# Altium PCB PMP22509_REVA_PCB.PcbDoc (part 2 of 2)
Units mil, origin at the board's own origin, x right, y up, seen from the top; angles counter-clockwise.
Board outline 3681.1 x 1505.91 mil, 2 copper layers (Top Layer, Bottom Layer), stack 62 mil thick; 70 components, 35 nets, 219 pads, 81 vias.
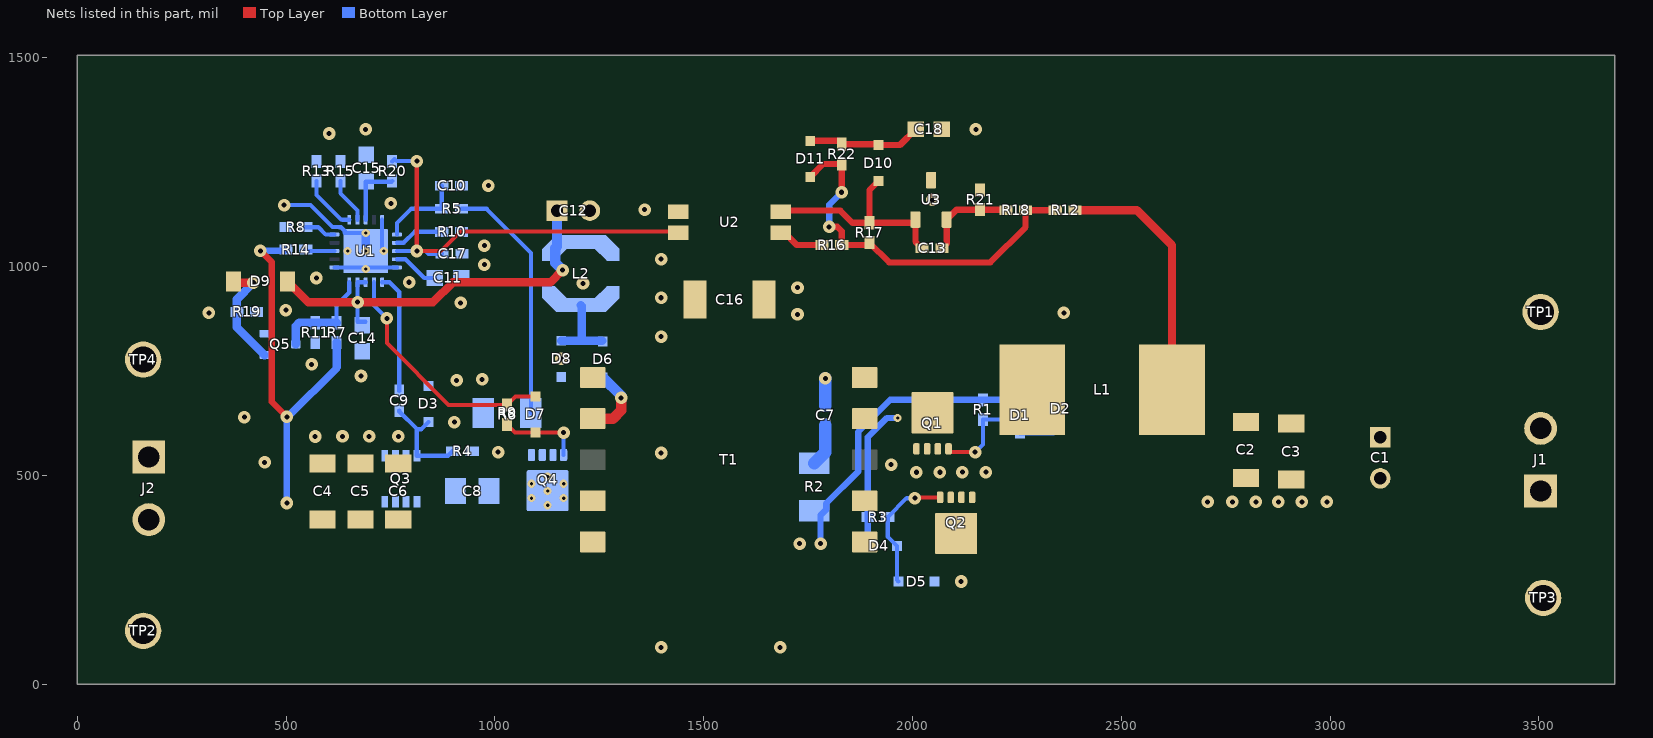
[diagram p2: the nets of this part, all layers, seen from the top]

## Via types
v1: diameter 30, hole 12, Top Layer to Bottom Layer, 65 vias
v2: diameter 19.68, hole 7.87, Top Layer to Bottom Layer, 12 vias
v3: diameter 30, hole 12, Top Layer to Bottom Layer, tented both sides, 3 vias
v4: diameter 19.68, hole 7.87, Top Layer to Bottom Layer, tented both sides, 1 vias

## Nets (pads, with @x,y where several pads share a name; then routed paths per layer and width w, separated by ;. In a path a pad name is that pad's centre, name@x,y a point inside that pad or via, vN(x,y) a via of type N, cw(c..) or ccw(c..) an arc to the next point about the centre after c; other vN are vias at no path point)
CS: Q4.1 Q4.2 Q4.3 R5.2 R9.2 | length 593.2
  Bottom Layer w10: R5.2@919.71,1138.57 980.05,1138.57 1086.04,1032.58 R9.2@1086.04,649.61
GND: C1.2 C2.2 C3.2 C16.1 C18.1 D2.2 D5.2 J1.1 Q1.1 Q1.2 Q1.3 Q2.1 Q2.2 Q2.3 R21.1 TP3.1 U3.3
  other v1: 1683.07,88.58 2116.14,246.06 2706.69,436.98 2765.94,436.83 2822.24,436.83 2876.19,436.98 2932.49,436.98 2992.13,437.01 2009.18,507.69 2065.48,507.69 2119.43,507.85 2175.73,507.85 1948.82,525.75 1724.42,885.83 2362.2,889.63 1724.42,949.9 2047.24,1160.13 2151.61,1329.03
NetC7_2: C7.2 R2.2 | length 101.6
  Bottom Layer w30: R2.2@1764.76,529.53 1791.37,556.14 C7.2@1791.37,620.08
NetC8_1: C8.1 Q4.5 Q4.6 Q4.7 Q4.8 Q4.9@1125.98,463.56 T1.2
  other v2: 1087.6,445.76 1164.37,445.76 1125.98,463 1087.6,480.25 1164.37,480.25 1125.98,497.49
  other v4: 1125.98,428.52
NetC8_2: C8.2 Q3.5 Q3.6 Q3.7 Q3.8
NetC9_1: C9.1 U1.11 | length 287.3
  Bottom Layer w10: U1.11@729.75,962.69 747.14,962.69 770.67,939.17 C9.1@770.67,702.5
NetC9_2: C9.2 D3.2 Q3.4 R4.1 | length 250.6
  Bottom Layer w10: C9.2@770.67,655.26 770.67,652.96 812.82,610.81 ; D3.2@840.69,627.95 823.55,610.81 812.82,610.81 ; R4.1@898.45,558.07 887.62,547.24 Q3.4@812.82,547.24 812.82,610.81
NetC10_2: C10.2 R5.1 U1.6 | length 204.3
  Bottom Layer w10: U1.6@765.18,1076.87 765.18,1104.43 799.32,1138.57 R5.1@872.46,1138.57 C10.2@872.46,1193.92
NetC11_1: C11.1 U1.9 | length 109.2
  Bottom Layer w10: U1.9@765.18,1017.81 785.65,1017.81 830.6,972.87 C11.1@855.73,972.87
NetC13_1: C13.1 R18.1 R21.2 U3.2 | length 226.7
  Top Layer w15: C13.1@2070.17,1043.98 2081.58,1055.4 U3.2@2081.58,1112.88 2105.2,1136.5 R21.2@2161.81,1136.5 R18.1@2224.91,1136.5
NetC13_2: C13.2 D10.2 R17.1 U2.2 U3.1 | length 525.4
  Top Layer w15: U2.2@1681.1,1134.35 1826.67,1134.35 1856.01,1105.01 R17.1@1896.57,1105.01 ; D10.2@1918.23,1204.72 1896.57,1183.07 R17.1@1896.57,1105.01 ; C13.2@2022.92,1043.98 2006.78,1060.13 U3.1@2006.78,1112.88 1998.91,1105.01 R17.1@1896.57,1105.01
NetC15_2: C15.2 R20.1 U1.3 | length 155.1
  Bottom Layer w10: U1.3@690.38,1112.3 690.38,1203.48 752.44,1203.48 R20.1@753.77,1204.82
NetC17_1: C17.1 R20.2 U1.8 U2.4 | length 1031.7
  Top Layer w10: v1@812.82,1243.56 v1(812.82,1252.92) ; v1@812.83,1243.55 v1(812.83,1037.5) 870.23,1037.5 917.08,1084.35 U2.4@1435.04,1084.35
  Bottom Layer w10: R20.2@753.77,1252.06 759.72,1258.01 764.81,1252.92 v1(812.82,1252.92) ; U1.8@765.18,1037.5 v1(812.83,1037.5) 834.06,1037.5 840.69,1030.87 C17.1@873.45,1030.87
NetC18_2: C18.2 D10.1 D11.2 R22.1 | length 272
  Top Layer w15: D11.2@1754.92,1301.32 1822.2,1301.32 R22.1@1830.21,1293.31 1916.26,1293.31 D10.1@1918.23,1291.34 1969.88,1291.34 C18.2@2007.28,1328.74
NetD1_2: D1.2 D2.1 Q1.4 R1.1 | length 357.9
  Top Layer w10: Q1.4@2086.02,563.63 2093.57,556.08 v1(2150,556.08)
  Bottom Layer w10: v1(2150,556.08) 2168.31,574.38 R1.1@2168.31,633.86 2223.42,633.86 D1.2@2256.89,600.39 2337.6,600.39 D2.1@2353.35,616.14
NetD4_2: D4.2 D5.1 Q2.4 R3.1 | length 309.5
  Top Layer w10: v1(2005.31,445.6) 2007.33,447.61 Q2.4@2065.85,447.61
  Bottom Layer w10: D5.1@1965.87,246.06 1962.6,249.34 D4.2@1962.6,331.18 1940.7,353.08 R3.1@1940.7,400.41 1985.89,445.6 v1(2005.31,445.6)
NetD6_1: D6.1 D8.1 L2.1 | length 185.8
  Bottom Layer w10: D6.1@1256.47,822.74 D6.1@1258,821.2
  Bottom Layer w20: D8.1@1158.66,822.74 1207.57,822.74 ; L2.1@1205.57,907.77 1207.57,905.78 1207.57,822.74 ; D6.1@1256.47,822.74 1207.57,822.74
NetD6_2: D6.2 T1.4 | length 173.3
  Top Layer w25: T1.4@1234.08,636.17 1282.6,636.17 1302.17,655.73 v3(1302.17,685.67)
  Bottom Layer w25: D6.2@1258,734.59 1302.17,690.43 v3(1302.17,685.67)
NetD7_1: D7.1 R6.1 U1.12 | length 584.1
  Top Layer w10: v1(741.14,875.98) 741.14,816.93 889.03,669.04 R6.1@1028.95,669.04 1049.23,689.31 D7.1@1096.95,689.31
  Bottom Layer w10: U1.12@710.06,962.69 710.06,907.06 v1(741.14,875.98)
NetD7_2: D7.2 Q4.4 R6.2 | length 196.8
  Top Layer w10: R6.2@1028.95,621.8 1048.05,602.7 D7.2@1096.95,602.7 v1(1164.37,602.7)
  Bottom Layer w10: Q4.4@1164.37,549.19 v1(1164.37,602.7)
NetD9_2: D9.2 Q5.1 R19.2 | length 265.9
  Top Layer w20: D9.2@373.89,964.57 376.89,961.57 v1(421.32,961.57)
  Bottom Layer w20: v1(421.32,961.57) 381.76,922.02 R19.2@381.76,891.86 381.76,854.71 Q5.1@448.2,788.28
NetD11_1: D11.1 R12.2 R16.2 R17.2 R18.2 R22.2 | length 927.7
  Top Layer w15: D11.1@1754.92,1214.71 1786.28,1246.06 R22.2@1830.21,1246.06 v1(1830.21,1178.2) ; v1(1800.2,1095.45) 1819.6,1095.45 1830.21,1084.84 R16.2@1830.21,1051.86 1890.67,1051.86 R17.2@1896.57,1057.76 1944.2,1010.13 2186.08,1010.13 2270.67,1094.72 R18.2@2270.67,1135.13 R12.2@2341.54,1135.13
  Bottom Layer w15: v1(1800.2,1095.45) 1800.2,1148.19 v1(1830.21,1178.2)
NetQ5_3: Q5.3 R7.2 R11.1 U1.15 | length 254.4
  Bottom Layer w10: R7.2@620.67,865.88 620.67,907.77 651.01,938.11 U1.15@651.01,962.69
  Bottom Layer w20: Q5.3@523,813.87 523,857.91 530.97,865.88 R11.1@569.48,865.88 R7.2@620.67,865.88
NetR8_1: R8.1 U1.20 | length 76.2
  Bottom Layer w10: R8.1@546.68,1094.58 576.86,1094.58 594.57,1076.87 U1.20@615.58,1076.87
NetR10_1: R10.1 U1.7 | length 118.2
  Bottom Layer w10: U1.7@765.18,1057.18 781.33,1057.18 807.6,1083.45 R10.1@872.46,1083.45
NetR13_1: R13.1 U1.1 | length 136.5
  Bottom Layer w10: R13.1@572.27,1204.82 572.27,1171.6 631.26,1112.61 634.3,1112.61 634.58,1112.34 638.96,1112.34 639,1112.3 U1.1@651.01,1112.3
NetR14_2: R14.2 U1.18 | length 70.2
  Bottom Layer w10: R14.2@546.68,1040.71 549.89,1037.5 U1.18@615.58,1037.5
NetR15_1: R15.1 U1.2 | length 109.5
  Bottom Layer w10: R15.1@629.75,1204.82 629.75,1175.69 670.69,1134.74 U1.2@670.69,1112.3
NetR16_1: R16.1 U2.1 | length 115.3
  Top Layer w15: U2.1@1681.1,1084.35 1690.05,1084.35 1722.54,1051.86 R16.1@1782.97,1051.86
PGND: C4.2 C5.2 C6.2 C10.1 C11.2 C12.2 C14.1 C15.1 C16.2 C17.2 D3.1 D8.2 J2.1 Q3.1 Q3.2 Q3.3 Q5.2 R4.2 R8.2 R9.1 R10.2 R11.2 R13.2 R15.2 R19.1 T1.5 TP4.1 U1.5 U1.10 U1.16 U1.21@690.38,1037.5 U2.3 | length 498
  Bottom Layer w10: v1(495.18,1147.58) 557.84,1147.58 610.68,1094.74 626.9,1094.74 627.17,1094.46 631.56,1094.46 640.26,1085.76 640.26,1081.38 640.83,1080.8 v2(690.38,1080.8) ; U1.16@615.58,998.13 686.44,998.13 v2(690.38,994.19) 694.32,998.13 U1.10@765.18,998.13 ; U1.5@729.75,1112.3 729.75,1041.43 v2(733.69,1037.5)
  Bottom Layer w20: v2(690.38,1037.5) v2(690.38,1080.8)
  other v1: 1397.64,88.58 448.61,531.43 1397.64,553.78 1007.3,556.14 569.48,593.33 634.81,593.73 698.82,593.73 768.76,593.73 902.56,627.54 399.65,639.76 907.9,727.94 968.91,730.32 679.13,738.19 561.02,765.87 1158.66,779.42 1397.64,832.29 314.96,889.63 499.43,895.67 917.74,913.51 1397.64,925.58 1210.71,959.78 572.27,972.87 974.56,1004.89 1397.64,1017.81 1358.27,1136.47 750.86,1151.57 984.25,1193.92 602.81,1318.9 690.38,1328.74
  other v2: 647.07,1037.5
  other v3: 794.25,962.69 974.41,1050.55
VDD: C12.1 C14.2 D9.1 L2.2 U1.13 U1.14 | length 996.1
  Top Layer w20: D9.1@502.83,964.57 552.44,914.96 v1(670.86,914.96) 851.63,914.96 899.2,962.52 1133.02,962.52 v1(1162.06,991.57)
  Bottom Layer w10: C14.2@689.56,868.04 670.86,868.04 v1(670.86,914.96) 670.86,962.52 U1.14@670.69,962.69 U1.13@690.38,962.69
  Bottom Layer w25: C12.1@1148.45,1134.13 1148.45,1048.48 L2.2@1144.55,1044.58 1144.55,1009.08 v1(1162.06,991.57)
VIN: C4.1 C5.1 C6.1 J2.2 R7.1 R14.1 T1.1 TP2.1 | length 1093.4
  Top Layer w15: v1(438.36,1038.08) 465.23,1011.21 465.23,676.54 v1(501.4,640.37)
  Bottom Layer w15: v1(438.36,1038.08) 496.8,1038.08 R14.1@499.43,1040.71 ; v1(501.4,434.06) v1(501.4,640.37) ; v1(501.4,640.37) 506.13,640.37 623.03,757.27 620.67,759.63 v1(501.4,640.37)
  Bottom Layer w20: 620.67,759.63 R7.1@620.67,818.64
VOUT: C1.1 C2.1 C3.1 J1.2 L1.2 R12.1 TP1.1 | length 613.3
  Top Layer w20: R12.1@2388.78,1135.13 2537.22,1135.13 2621.06,1051.28 L1.2@2621.06,704.95
VSEC1: C7.1 D4.1 L1.1 Q1.5 Q1.6 Q1.7 Q1.8 Q1.9 R3.2 T1.6 T1.7 | length 423
  Bottom Layer w15: D4.1@1875.98,331.18 1892.64,347.83 1892.64,591.76 1938.65,637.78 v2(1964.19,637.78)
  Bottom Layer w30: C7.1@1791.37,667.32 v1(1791.37,732.26)
VSEC2: D1.1 Q2.5 Q2.6 Q2.7 Q2.8 Q2.9 R1.2 R2.1 T1.9 T1.10 | length 726.4
  Bottom Layer w10: D1.1@2250.98,681.1 D1.1@2256.89,687.01
  Bottom Layer w15: v1(1779.56,336.66) 1779.56,404.7 1793.4,418.54 1793.4,433.04 1869.76,509.4 1869.76,604.33 1946.53,681.1 R1.2@2168.31,681.1 D1.1@2250.98,681.1
  other v1: 1729.33,336.66
pads on no net: Q1.9A Q1.9B Q1.9C Q1.9D Q2.9A Q2.9B Q2.9C Q2.9D Q4.9@1087.6,442.89 Q4.9@1099.9,463 Q4.9@1099.9,497.49 Q4.9@1113.19,442.89 Q4.9@1125.98,476.25 Q4.9@1138.78,442.89 Q4.9@1152.07,463 Q4.9@1152.07,497.49 Q4.9@1164.37,442.89 T1.3 T1.8 U1.4 U1.17 U1.19 U1.21@663.02,1010.13 U1.21@663.02,1064.86 U1.21@717.74,1010.13 U1.21@717.74,1064.86

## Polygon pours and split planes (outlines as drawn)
GND on Top Layer "TOP_LAYER_GND_P022" (solid, remove dead copper, pour order 22): 1614.17,1448.86 1641.69,1476.38 3498.57,1476.38 3636.37,1338.58 3636.37,73.38 3592.52,29.53 1623.41,29.53 1614.17,38.77
PGND on Top Layer "TOP_LAYER_PGND_P018" (solid, remove dead copper, pour order 18): 71.85,29.53 32.48,68.9 32.48,1442.26 66.6,1476.38 1476.38,1476.38 1505.91,1446.85 1505.91,40.22 1495.21,29.53 1253.07,29.53
VOUT on Top Layer "TOP_LAYER_VOUT_P016" (solid, remove dead copper, pour order 16): 3602.36,1476.38 3636.37,1442.37 3636.37,541.34 2459.91,541.34 2443.9,556.67 2443.9,1476.38
VSEC1 on Top Layer "TOP_LAYER_VSEC1_P014" (solid, remove dead copper, pour order 14): 2411.38,558.07 2431.1,577.79 2431.1,823.01 2417.5,836.61 1762.6,836.61 1749.02,823.03 1749.02,690.3 1848.76,590.55 2105.52,590.55 2138,558.07
VSEC2 on Top Layer "TOP_LAYER_VSEC2_P010" (solid, remove dead copper, pour order 10): 1938.25,472.44 1994.87,415.82 2161.61,415.82 2166.46,410.97 2166.46,298.71 2163.03,295.28 2070.17,295.28 1705.71,295.28 1686.02,314.96 1686.02,346.46 1812.01,472.44
NetC8_1 on Top Layer "TOP_LAYER_NETC8_1_P002" (solid, remove dead copper, pour order 2): 1282.48,412.74 1265.36,395.62 1070.82,395.62 1055.02,411.42 1055.02,501.97 1069.73,516.68 1282.48,516.68
VIN on Top Layer "TOP_LAYER_VIN_P000" (solid, remove dead copper, pour order 0): 33.44,463.56 32.48,462.6 32.48,68.9 71.85,29.53 1282.61,29.53 1282.48,365.9 1261.73,386.66 1021.81,386.66 944.91,463.56
GND on Bottom Layer "BOTTOM_LAYER_GND_P024" (solid, remove dead copper, pour order 24): 1614.17,1448.86 1641.69,1476.38 3602.36,1476.38 3636.37,1442.37 3636.37,73.38 3592.52,29.53 1623.41,29.53 1614.17,38.77
PGND on Bottom Layer "BOTTOM_LAYER_PGND_P020" (solid, remove dead copper, pour order 20): 71.85,29.53 32.48,68.9 32.48,1442.26 66.6,1476.38 1476.38,1476.38 1505.91,1446.85 1505.91,40.22 1495.21,29.53 1253.07,29.53
VSEC2 on Bottom Layer "BOTTOM_LAYER_VSEC2_P012" (solid, remove dead copper, pour order 12): 1705.71,295.28 1686.02,314.96 1686.02,441.37 1704.14,459.48 1814.14,459.48 1833.66,439.96 1833.66,313.36 1815.58,295.28
CS on Bottom Layer "BOTTOM_LAYER_CS_P008" (solid, remove dead copper, pour order 8): 1049.45,531.5 1154.53,531.5 1154.53,701.77 1049.45,701.77
NetC8_2 on Bottom Layer "BOTTOM_LAYER_NETC8_2_P006" (solid, remove dead copper, pour order 6): 937.99,404.27 945.87,412.15 945.87,506.87 937.99,514.74 716.96,514.74 708.49,506.26 708.49,417.11 721.32,404.27
NetC8_1 on Bottom Layer "BOTTOM_LAYER_NETC8_1_P004" (solid, remove dead copper, pour order 4): 1174.21,404.27 1192.91,422.97 1192.91,500.17 1176.4,516.68 961.52,516.68 957.68,512.83 957.68,412.76 966.16,404.27

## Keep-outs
Keep-Out Layer:
  text ".Layer_Name" at 577,-858.49 h60

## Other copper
Top Layer:
  text ".Layer_Name" at 577,-858.49 h60
Bottom Layer:
  text ".Layer_Name" at 577,-858.49 h60

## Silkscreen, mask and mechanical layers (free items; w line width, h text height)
Top Overlay:
  text "'.PRJ_Number'.PCB_Rev" at 86.28,1368.11 h108.27
  text ".Layer_Name" at 577,-858.49 h60
Bottom Overlay:
  text ".Layer_Name" at 577,-858.49 h60
Top Paste:
  text ".Layer_Name" at 577,-858.49 h60
Bottom Paste:
  text ".Layer_Name" at 577,-858.49 h60
Top Solder:
  text ".Layer_Name" at 577,-858.49 h60
  text ".Layer_Name" at 577,-858.49 h60
Bottom Solder:
  text ".Layer_Name" at 577,-858.49 h60
Drill Guide:
  text ".Layer_Name" at 577,-858.49 h60
M1 Board Outline:
  the board outline again, w10
  text ".Layer_Name" at 577,-858.49 h60
M2 Board Dimensions:
  rectangle: 0,-275 125,-150
  rectangle: 125,-400 500,-275
  lines w7: 0,-275 1000,-275 ; 125,-400 125,-150 ; 250,-400 250,-150 ; 500,-400 500,-150 ; 750,-400 750,-150 ; 0,-400 1000,-400 1000,-150 0,-150 0,-400
  text ".Layer_Name" at 577,-858.49 h60
M3 3D STEP Top:
  text ".Layer_Name" at 577,-858.49 h60
M4 3D STEP Bottom:
  text ".Layer_Name" at 577,-858.49 h60
M5 Assembly Top:
  lines w10: -292,-930.17 6308,-930.17 ; -292,-726.83 6310,-726.83 ; -292,-523.5 -292,-1133.5 3713,-1133.5 6310,-1133.5 6310,-523.5 -291.5,-523.5 -291.5,-1133.5 1284,-1133.5 ; 2173,-1133.5 2173,-523.5 ; 3440,-726.83 3440,-523.5 ; 4280,-726.83 4280,-523.5 ; 4902,-1140 4902,-937.17
  text "COMPONENTS MARKED 'DNP' SHOULD NOT BE POPULATED." at 1153.5,-318.5 h60
  text "ASSEMBLY VARIANT:" at 1153,-434 h60
  text ".VariantName" at 2189,-434 h60
  text "PCB VIEWED FROM TOP SIDE" at -228.5,-655.67 h60
  text "BOARD #:" at 2248,-655.67 h60
  text ".PRJ_Number" at 2793.5,-655.67 h60
  text "REV:" at 3638,-655.67 h60
  text ".PCB_Rev" at 3929.5,-655.67 h60
  text "SVN REV:" at 4476,-655.67 h60
  text ".VersionControl_RevNumber" at 4982,-655.67 h60
  text "TID #:" at 2248,-859 h60
  text ".TID" at 2793.5,-859 h60
  text "PLOT NAME =" at -228.5,-1064.34 h60
  text ".plot_File_Name" at 577,-1064.34 h60
  text "GENERATED    :" at 2250,-1064.34 h60
  text ".Print_Date" at 3119.5,-1064.34 h60
  text ".Print_Time" at 3848.5,-1064.34 h60
  text "TEXAS INSTRUMENTS" at 5113,-1064.34 h60
M6 Assembly Bottom:
  lines w10: -292.5,-727.33 6309.5,-727.33 ; -290.5,-930.67 6309.5,-930.67 ; 1115.5,-1140.5 1115.5,-937.67 ; 1737.5,-727.33 1737.5,-524 ; 2577.5,-727.33 2577.5,-524 ; 3844.5,-1134 3844.5,-524 ; 4733.5,-1134 6309,-1134 6309,-524 -292.5,-524 -292.5,-1134 2304.5,-1134 6309.5,-1134 6309.5,-524
  text "COMPONENTS MARKED 'DNP' SHOULD NOT BE POPULATED." at 6102,-318 h60
  text ".VariantName" at 5058,-434 h60
  text "ASSEMBLY VARIANT:" at 6097,-434 h60
  text ".VersionControl_RevNumber" at 1035.5,-656.17 h60
  text "SVN REV:" at 1541.5,-656.17 h60
  text ".PCB_Rev" at 2088,-656.17 h60
  text "REV:" at 2379.5,-656.17 h60
  text ".PRJ_Number" at 3224,-656.17 h60
  text "BOARD #:" at 3769.5,-656.17 h60
  text "PCB VIEWED FROM BOTTOM SIDE" at 6246,-656.17 h60
  text ".TID" at 3224,-859.5 h60
  text "TID #:" at 3769.5,-859.5 h60
  text "TEXAS INSTRUMENTS" at 904.5,-1064.84 h60
  text ".Print_Time" at 2169,-1064.84 h60
  text ".Print_Date" at 2898,-1064.84 h60
  text "GENERATED    :" at 3767.5,-1064.84 h60
  text ".plot_File_Name" at 5440.5,-1064.84 h60
  text "PLOT NAME =" at 6246,-1064.84 h60
M9 Title Sheet:
  drawing of 57 lines, arcs and shapes, not listed
  text "1" at 739.84,8036.5 h70
  text "2" at 3235.5,8036.5 h70
  text "3" at 5724.84,8036.5 h70
  text "4" at 8231.51,8036.5 h70
  text "5" at 10730.5,8036.5 h70
  text "6" at 13235.5,8036.5 h70
  text "A" at -416.5,6893.5 h70
  text "A" at 14383.5,6893.5 h70
  text "B" at -416.5,4513.5 h70
  text "B" at 14383.5,4513.5 h70
  text "C" at -416.5,2138.5 h70
  text "C" at 14383.5,2138.5 h70
  text "PROJECT TITLE:" at 11343.5,277.5 h45
  text ".PRJ_Title" at 11393.5,144.17 h70
  text "DESIGNED FOR:" at 11343.5,-23.5 h45
  text ".PRJ_Customer" at 11393.5,-163.5 h70
  text "D" at -416.5,-231.5 h70
  text "D" at 14383.5,-231.5 h70
  text "FILE NAME:" at 11343.5,-323.5 h45
  text ".PCB_File_Name_No_Path" at 11393.5,-443.5 h70
  text "Texas Instruments (TI) and/or its licensors do not warrant the accuracy or completeness of this specification" at 6374,-605.34 h45
  text "ENGINEER:" at 11343.5,-613.5 h45
  text "LAYOUT BY:" at 12848.5,-613.5 h45
  text "or any information contained therein. TI and/or its licensors do not warrant that this design will meet" at 6329.01,-718 h45
  text ".PRJ_Engineer" at 11393.5,-768.49 h70
  text ".PCB_Layout" at 12899,-768.49 h70
  text "the specifications, will be suitable for your application or fit for any particular purpose, or will operate in" at 6329.01,-830.67 h45
  text ".Layer_Name" at 577,-858.49 h60
  text "ALTIUM DESIGNER VERSION:" at 12848.5,-923.5 h45
  text "an implementation. TI and/or its licensors do not warrant that the design is production worthy. You should" at 6329.01,-943.33 h45
  text "completely validate and test your design implementation to confirm the system functionality for your application." at 6374,-1056 h45
  text ".print_Scale" at 11393.5,-1056.83 h70
  text ".Application_BuildNumber" at 12899,-1056.83 h70
  text "1" at 739.84,-1263.5 h70
  text "2" at 3235.5,-1263.5 h70
  text "3" at 5724.84,-1263.5 h70
  text "4" at 8231.51,-1263.5 h70
  text "5" at 10730.5,-1263.5 h70
  text "6" at 13235.5,-1263.5 h70
M10 Fab Notes:
  drawing of 189 lines, arcs and shapes, not listed
  text "DESIGN INFORMATION" at 12382.02,6356.17 h60
  text "MIN. TRACK WIDTH:" at 11737.46,6224.05 h60
  text "8" at 12833.7,6224.05 h60
  text "MIL" at 12988.46,6224.05 h60
  text "MIN. CLEARANCE:" at 11737.46,6099.92 h60
  text "0.2" at 12773.7,6099.93 h60
  text "mm" at 12988.46,6099.92 h60
  text "MIN. VIA PAD SIZE:" at 11737.46,5975.8 h60
  text "24" at 12803.71,5975.8 h60
  text "MIL" at 12988.46,5975.8 h60
  text "0.05mm (2MIL)" at 12432.46,5845.9 h60
  text "MINIMUM ANNULAR RING" at 11408.23,5837.67 h60
  text "EXTERNAL" at 13140.46,5837.67 h60
  text "PER" at 11608.23,5727.55 h60
  text "IPC-D-275 CLASS 2 LEVEL C" at 11828.23,5727.54 h60
  text "MIL, HOLES" at 13316.46,5627.07 h60
  text "+/-" at 12924,5618.48 h60
  text "+/-" at 13778,5618.48 h60
  text "REGISTRATION TOLERANCES:" at 11408.23,5617.42 h60
  text "METAL" at 12608,5617.42 h60
  text "5" at 13184.2,5617.42 h60
  text "3" at 14017.2,5617.42 h60
  text "MIL" at 14133.46,5617.42 h60
  text "HOLE SIZE TOLERANCE (UNLESS OTHERWISE SPECIFIED):" at 11408.23,5519.1 h60
  text "+/-" at 13778,5516.23 h60
  text "3" at 14017.2,5515.17 h60
  text "MIL" at 14133.46,5515.17 h60
  text "MATERIAL:" at 11333.46,5377.52 h60
  text "FR-4 High Tg" at 12319.9,5249 h60
  text "X" at 12175.46,5241.01 h60
  text "FR-408" at 11754.46,5236.49 h60
  text "OTHER" at 13242.46,5236.49 h60
  text "62 MIL (1.6mm) +/-10%" at 12074.56,5093.46 h60
  text "X" at 11954.46,5091.01 h60
  text "THICKNESS:" at 11408.23,5085.24 h60
  text "OTHER" at 13359.46,5085.24 h60
  text "TOLERANCE:" at 11408.23,4946.92 h60
  text "X" at 12256.46,4946.92 h60
  text "ANSI IPC-6012 TYPE 3 CLASS 2" at 12434.48,4946.92 h60
  text "OTHER +/-" at 12434.46,4802.73 h60
  text "BOW & TWIST:" at 11408.23,4657.54 h60
  text "X" at 12256.46,4657.54 h60
  text "ANSI IPC-6012 TYPE 3 CLASS 2" at 12434.48,4657.54 h60
  text "OTHER +/-" at 12434.46,4510.85 h60
  text "DRILLING:" at 11333.46,4380.23 h60
  text "NC_DRILL FILES" at 13094.46,4275.04 h60
  text "REFERENCE:" at 11408.23,4271.1 h60
  text "X" at 12065.46,4271.01 h60
  text "AS SHOWN" at 12243.46,4271.1 h60
  text "X" at 12966.46,4271.1 h60
  text "OTHER" at 13392.46,4128.85 h60
  text "PTH COPPER THICKNESS:" at 11407.91,4125.32 h60
  text "X" at 12547.14,4125.32 h60
  text "20-30 um" at 12675.14,4125.32 h60
  text "BOARD FINISH:" at 11333.46,3977.73 h60
  text "SILKSCREEN:" at 11488.68,3867.6 h60
  text "X" at 12446.46,3867.6 h60
  text "TOP" at 12563.46,3867.6 h60
  text "X" at 12956.46,3867.6 h60
  text "BOTTOM" at 13074.46,3867.6 h60
  text "SILKSCREEN COLOR:" at 11488.68,3712.41 h60
  text "X" at 12445.46,3712.41 h60
  text "WHITE" at 12563.46,3712.41 h60
  text "OTHER" at 13074.46,3712.41 h60
  text "X" at 12576.46,3568.96 h60
  text "GREEN" at 12694.46,3568.96 h60
  text "OTHER" at 13312.46,3568.96 h60
  text "SOLDER RESIST COLOR:" at 11488.68,3562.1 h60
  text "X" at 12576.46,3414.71 h60
  text "MATTE" at 12694.46,3414.71 h60
  text "SEMI-GLOSS" at 13312,3414.07 h60
  text "IMMERSION GOLD (ENIG)" at 12394.46,3241.94 h60
  text "ENEPIG" at 13732,3234.72 h60
  text "SURFACE FINISH:" at 11333.46,3233.72 h60
  text "X" at 12216.46,3233.72 h60
  text "IMM. TIN/SILVER OR EQUIV" at 11663,3096.4 h60
  text "OTHER" at 13094.46,3092.47 h60
  text "ARRAY/PANEL:" at 11333.46,2937.09 h60
  text "CUT AND TRIM PER M1 BOARD OUTLINE" at 12394.46,2928.87 h60
  text "N.C. ROUTE" at 12394.46,2792.9 h60
  text "X" at 13082.46,2792.9 h60
  text "V. SCORE" at 13260.46,2792.9 h60
  text "CERTIFICATION:" at 11333.46,2663.77 h60
  text "MATERIALS AND WORKMANSHIP FOR ALL PCBS" at 12058.46,2663.77 h60
  text "TO MEET OR EXCEED THE REQUIREMENTS OF:" at 12058.46,2569.71 h60
  text "X" at 11695.97,2441.08 h60
  text "ANSI IPC-A-600F CLASS ->" at 11823.96,2441.08 h60
  text "X" at 13471.97,2441.08 h60
  text "2" at 13581.96,2441.08 h60
  text "1" at 13266.96,2439.58 h60
  text "3" at 13935.96,2439.58 h60
  text "X" at 12507.97,2293.39 h60
  text "RoHS" at 12635.96,2293.39 h60
  text "OTHER" at 13280.36,2293.39 h60
  text "PER ORDER" at 13677.42,2293.39 h60
  text "ALL BOARDS MUST MEET OR EXCEED UL94-V0 REQUIREMENTS." at 11361,2139.57 h60
  text "PCB MUST BEAR THE UL94V-0 UL REGISTERED MATERIAL ID NUMBER" at 11361,2023.5 h60
  text "ADDITIONAL REQUIREMENTS:" at 11333.46,1854.08 h60
  text "MICROSECTION:" at 11408.23,1746.95 h60
  text "YES" at 12313.96,1746.95 h60
  text "REQUIRED" at 13175.46,1602.62 h60
  text "BARE BOARD ELEC. TEST:" at 11408.23,1599.76 h60
  text "NONE" at 12713.96,1599.76 h60
  text "X" at 13057.46,1599.76 h60
  text "PER ORDER" at 13767.46,1599.76 h60
  text "XX MIL VIAS REQUIRE NON-CONDUCTIVE FILL AND PLANARIZE" at 11576.38,1394.82 h59
  text "XX MIL VIAS REQUIRE CONDUCTIVE FILL AND PLANARIZE" at 11584.38,1290.84 h60
  text "OUTER XX MIL TRACES REQUIRE 50 OHM SINGLE-ENDED IMPEDANCE" at 11583.39,1127.46 h58
  text "LAYER 2 & 3 (INNER LAYERS) XX MIL WIDE, XX MIL SPACE / TRACES REQUIRE 100 OHM DIFFERENTIAL IMPEDANCE" at 11575.39,891.74 h60
  text ".Layer_Name" at 577,-858.49 h60
M11 Gerber Information:
  lines w10: -292,-930.17 6308,-930.17 ; -292,-726.83 6310,-726.83 ; -292,-523.5 -292,-1133.5 3713,-1133.5 6310,-1133.5 6310,-523.5 -291.5,-523.5 -291.5,-1133.5 1284,-1133.5 ; 2173,-1133.5 2173,-523.5 ; 3440,-726.83 3440,-523.5 ; 4280,-726.83 4280,-523.5 ; 4902,-1140 4902,-937.17
  text "ALL ARTWORK VIEWED FROM TOP SIDE" at -228.5,-655.67 h60
  text "BOARD #:" at 2248,-655.67 h60
  text ".PRJ_Number" at 2793.5,-655.67 h60
  text "REV:" at 3638,-655.67 h60
  text ".PCB_Rev" at 3929.5,-655.67 h60
  text "SVN REV:" at 4476,-655.67 h60
  text ".VersionControl_RevNumber" at 4982,-655.67 h60
  text "LAYER NAME =" at -228.5,-858.49 h60
  text "TID #:" at 2248,-859 h60
  text ".TID" at 2793.5,-859 h60
  text "PLOT NAME =" at -228.5,-1064.34 h60
  text ".plot_File_Name" at 577,-1064.34 h60
  text "GENERATED    :" at 2250,-1064.34 h60
  text ".Print_Date" at 3119.5,-1064.34 h60
  text ".Print_Time" at 3848.5,-1064.34 h60
  text "TEXAS INSTRUMENTS" at 5113,-1064.34 h60
M12 Stackup:
  drawing of 776 lines, arcs and shapes, not listed
  text "Layer" at 9811.59,7672.44 h60
  text "Name" at 10221.51,7672.44 h60
  text "Material" at 11151.25,7672.44 h60
  text "Thickness" at 12011.02,7672.44 h60
  text "Constant" at 12660.85,7672.44 h60
  text "Board Layer Stack" at 13230.71,7672.44 h60
  text "Board Layer Stack" at 14350.4,7672.44 h60
  text "Board Layer Stack" at 15470.08,7672.44 h60
  text "Board Layer Stack" at 16589.76,7672.44 h60
  text "Board Layer Stack" at 17709.45,7672.44 h60
  text "1" at 9811.59,7552.44 h60
  text "Top Overlay" at 10221.51,7552.44 h60
  text "2" at 9811.59,7432.44 h60
  text "Top Solder" at 10221.51,7432.44 h60
  text "Solder Resist" at 11151.25,7432.44 h60
  text "0.40mil" at 12011.02,7432.44 h60
  text "3.5" at 12660.85,7432.44 h60
  text "3" at 9811.59,7312.44 h60
  text "Top Layer" at 10221.51,7312.44 h60
  text "Copper" at 11151.25,7312.44 h60
  text "1.40mil" at 12011.02,7312.44 h60
  text "4" at 9811.59,7192.44 h60
  text "Dielectric1" at 10221.51,7192.44 h60
  text "FR-4" at 11151.25,7192.44 h60
  text "59.20mil" at 12011.02,7192.44 h60
  text "4.8" at 12660.85,7192.44 h60
  text "5" at 9811.59,7072.44 h60
  text "Bottom Layer" at 10221.51,7072.44 h60
  text "Copper" at 11151.25,7072.44 h60
  text "1.40mil" at 12011.02,7072.44 h60
  text "6" at 9811.59,6952.44 h60
  text "Bottom Solder" at 10221.51,6952.44 h60
  text "Solder Resist" at 11151.25,6952.44 h60
  text "0.40mil" at 12011.02,6952.44 h60
  text "3.5" at 12660.85,6952.44 h60
  text "7" at 9811.59,6832.44 h60
  text "Bottom Overlay" at 10221.51,6832.44 h60
  text ".Layer_Name" at 577,-858.49 h60
M13 Component Bodies Top:
  text ".Layer_Name" at 577,-858.49 h60
M14 Component Bodies Bottom:
  text ".Layer_Name" at 577,-858.49 h60
M15 Courtyards Top:
  text ".Layer_Name" at 577,-858.49 h60
M16 Courtyards Bottom:
  text ".Layer_Name" at 577,-858.49 h60
Drill Drawing:
  circle w10: c5363.63,3220.32 r27.59
  lines w10: 5336.04,2820.2 5391.23,2820.2 5391.23,2875.39 5336.04,2875.39 5336.04,2820.2 ; 5336.04,2944.37 5363.63,2958.17 5391.23,2944.37 5377.43,2971.97 5391.23,2999.56 5363.63,2985.76 5336.04,2999.56 5349.83,2971.97 5336.04,2944.37 ; 5336.04,3123.74 5391.23,3123.74 5363.63,3068.55 5336.04,3123.74 ; 5336.04,3330.7 5349.83,3330.7 5363.63,3316.9 5377.43,3330.7 5391.23,3330.7 5377.43,3344.5 5391.23,3358.29 5377.43,3358.29 5363.63,3372.09 5349.83,3358.29 5336.04,3358.29 5349.83,3344.5 5336.04,3330.7
  lines w12: 5286,2782.94 8516.52,2782.94 ; 5286,3403.82 8516.52,3403.82 ; 5623.86,2658.77 5623.86,3528 ; 5955.86,2658.77 5955.86,3528 ; 6592.42,2658.77 6592.42,3528 ; 6851.53,2658.77 6851.53,3528 ; 7226.68,2658.77 7226.68,3528 ; 7950.06,2658.77 7950.06,3528 ; 5286,2658.77 8516.52,2658.77 8516.52,3528 5286,3528 5286,2658.77
  text "Symbol" at 5360.51,3441.08 h72
  text "Quantity" at 5661.11,3441.08 h72
  text "Finished Hole Size" at 5993.12,3441.08 h72
  text "Plated" at 6629.67,3441.08 h72
  text "Hole Type" at 6888.78,3441.08 h72
  text "Drill Layer Pair" at 7263.93,3441.08 h72
  text "Hole Tolerance" at 7987.32,3441.08 h72
  text "13" at 5661.11,3316.9 h60
  text "7.87mil (0.200mm)" at 5993.12,3316.9 h60
  text "PTH" at 6629.67,3316.9 h60
  text "Round" at 6888.78,3316.9 h60
  text "Top Layer - Bottom Layer" at 7263.93,3316.9 h60
  text "68" at 5661.11,3192.72 h60
  text "12.00mil (0.305mm)" at 5993.12,3192.72 h60
  text "PTH" at 6629.67,3192.72 h60
  text "Round" at 6888.78,3192.72 h60
  text "Top Layer - Bottom Layer" at 7263.93,3192.72 h60
  text "4" at 5661.11,3068.55 h60
  text "29.53mil (0.750mm)" at 5993.12,3068.55 h60
  text "PTH" at 6629.67,3068.55 h60
  text "Round" at 6888.78,3068.55 h60
  text "Top Layer - Bottom Layer" at 7263.93,3068.55 h60
  text "4" at 5661.11,2944.37 h60
  text "51.18mil (1.300mm)" at 5993.12,2944.37 h60
  text "PTH" at 6629.67,2944.37 h60
  text "Round" at 6888.78,2944.37 h60
  text "Top Layer - Bottom Layer" at 7263.93,2944.37 h60
  text "4" at 5661.11,2820.2 h60
  text "63.00mil (1.600mm)" at 5993.12,2820.2 h60
  text "PTH" at 6629.67,2820.2 h60
  text "Round" at 6888.78,2820.2 h60
  text "Top Layer - Bottom Layer" at 7263.93,2820.2 h60
  text "93 Total" at 5661.11,2696.02 h60
  text ".Layer_Name" at 577,-858.49 h60
M17 Embedded Cavity:
  text ".Layer_Name" at 577,-858.49 h60
M18 Embedded Assembly:
  text ".Layer_Name" at 577,-858.49 h60
M19 Embedded Keepout:
  text ".Layer_Name" at 577,-858.49 h60

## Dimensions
0,0 to 0,1505.91 on M2 Board Dimensions
0,0 to 3681.1,0 on M2 Board Dimensions
0,-400 to 1000,-400 on M2 Board Dimensions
